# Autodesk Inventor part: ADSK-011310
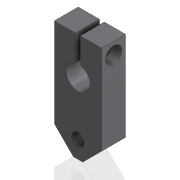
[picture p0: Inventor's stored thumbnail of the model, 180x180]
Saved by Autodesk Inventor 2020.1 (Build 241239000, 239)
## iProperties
Created: 1999-11
Part Number: ADSK-011310
Material: Acier doux
Description: PLT-04,FC,CP,06,012,028,ARM,CRANK
Document SubType Name: Modeling
Designer: sspink
Density: 7.86 g/cm^3
Appearance: Metal-Steel(Polish)
Mass: 220.951 g
Surface Area: 89.3546 cm^2
Volume: 28.1108 cm^3
Control State: 0
Checked Out: False
Last Check In By: sspink
Last Check In Date: 1999-12-16
Master: False
Shininess: 0.0
Length Units: 11269
Angle Units: 11279
Time Units: 11290
Mass Units: 11283
Length Display Precision: 3
Angle Display Precision: 2
Compacted: True
Material Desc: FLAT,CRS,0.625 X 1.25
Cutlength: 2.88
Material_number: A084284
Dimensions: 31,8x72,5x16 mm
Mass: 0,221 kg
DocNumber: ADSK-011310.ipt
Folder: 01 - Themengebiete\Simplification\01 - Packaging machine\
VDS_Category: 3D Komponenten
Density: 0.0
Volumn: 0.0
Area: 0.0
PropertySet Name: Model Information
Author: sspink
Revision Number: -
Title: PLT-04,FC,CP,06,012,028,ARM,CRANK
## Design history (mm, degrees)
node "Solide1"
  node "Extrusion1" dims "d4" = 16, "d5" = 0
  node "Hole1" dims "d6" = 8.376, "d7" = 9.525, "d8" = 6.35, "d9" = 60 deg, "d10" = 19.05, "d11" = 118 deg, "d35" = 20
  node "Chamfer1" dims "d14" = 12.7, "d15" = 12.7, "d34" = 45 deg
  node "Extrusion2" dims "d18" = 15.875, "d19" = 0
  node "Hole2" dims "d22" = 6.6, "d23" = 11, "d24" = 6.8, "d25" = 60 deg, "d26" = 19.05, "d27" = 118 deg, "d36" = 6
  node "Hole3" dims "d28" = 4.917, "d29" = 13.4874, "d30" = 8.7376, "d31" = 60 deg, "d32" = 17.1, "d33" = 118 deg, "d37" = 12
sketch "Sketch1"
  geometry: L1 (0, 0)-(15.875, 0); L2 (0, 0)-(-15.875, 0); L3 (-15.875, 0)-(-15.875, -47.5); L4 (-15.875, -47.5)-(15.875, -47.5); L5 (15.875, -47.5)-(15.875, 0); L6 (-15.875, 0)-(-15.875, 25); L7 (-15.875, 25)-(15.875, 25); L8 (15.875, 25)-(15.875, 0); C1 r 8 at (0, 0); A1 r 7.937 centre (0, 0) between (2.381, -7.572) and (-2.381, -7.572) reference
  constraints: 16 end point, 3 parallel, 3 perpendicular, 2 collinear, 1 centre point, 1 coincident, 1 horizontal
  dimensions: "d0" = 16 diameter of C1; "d1" = 31.75 distance of L6.end L7.end; "d2" = 25 distance of L7.end L1.end; "d3" = 47.5 distance of L4.end L1.end
sketch "Sketch2"
  geometry: L1 (15.875, -47.5)-(-15.875, -47.5) reference; L2 (0, 0)-(0, -36); C1 r 8 at (0, 0) reference
  constraints: 2 end point, 1 perpendicular
  dimensions: "d12" = 36 distance of L2.end L2.start
workaxis "Arbeitsachse1"
workplane "Arbeitsebene1"
sketch "Sketch4"
  geometry: L1 (16, 0)-(0, 0) reference; 2 further points
  constraints: 1 midpoint, 1 vertical alignment
  dimensions: "d20" = 8 distance from line of point (8, -8) L1
sketch "Sketch5"
  geometry: C1 r 3.3 at (8, -8) reference; 1 further point
  constraints: 1 coincident
node "Corps solides"
node "Corps surfaciques"
sketch "Sketch3"
  geometry: L1 (-15.875, 25)-(15.875, 25) reference; L2 (0, 0)-(0, 25); L3 (1.588, 7.841)-(1.588, 25); L4 (-1.587, 7.841)-(-1.587, 25); A1 r 8 centre (0, 0) between (1.588, 7.841) and (-1.587, 7.841) reference
  constraints: 6 end point, 2 point on circle, 2 point on line, 1 midpoint, 1 parallel, 1 perpendicular
  dimensions: "d16" = 1.5875 distance between parallel lines of L2 L4; "d17" = 1.5875 distance between parallel lines of L3 L2 (= d16)
other parameters: "d38" = 0
